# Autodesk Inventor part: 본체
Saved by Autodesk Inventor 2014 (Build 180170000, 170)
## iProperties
Created: 2026-05
Part Number: 본체
Material: 알루미늄 6061
Document SubType Name: Modeling
Designer: dg
Density: 2.71 g/cm^3
Appearance: 알루미늄 - 평지
Author: jhkim
Creation Date: 2026-04-23
Sending System: Autodesk Inventor 2027
Preprocessor: ST-DEVELOPER v20.1
Author: dg
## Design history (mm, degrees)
node "본체1"
node "솔리드1"
node "기준1"
